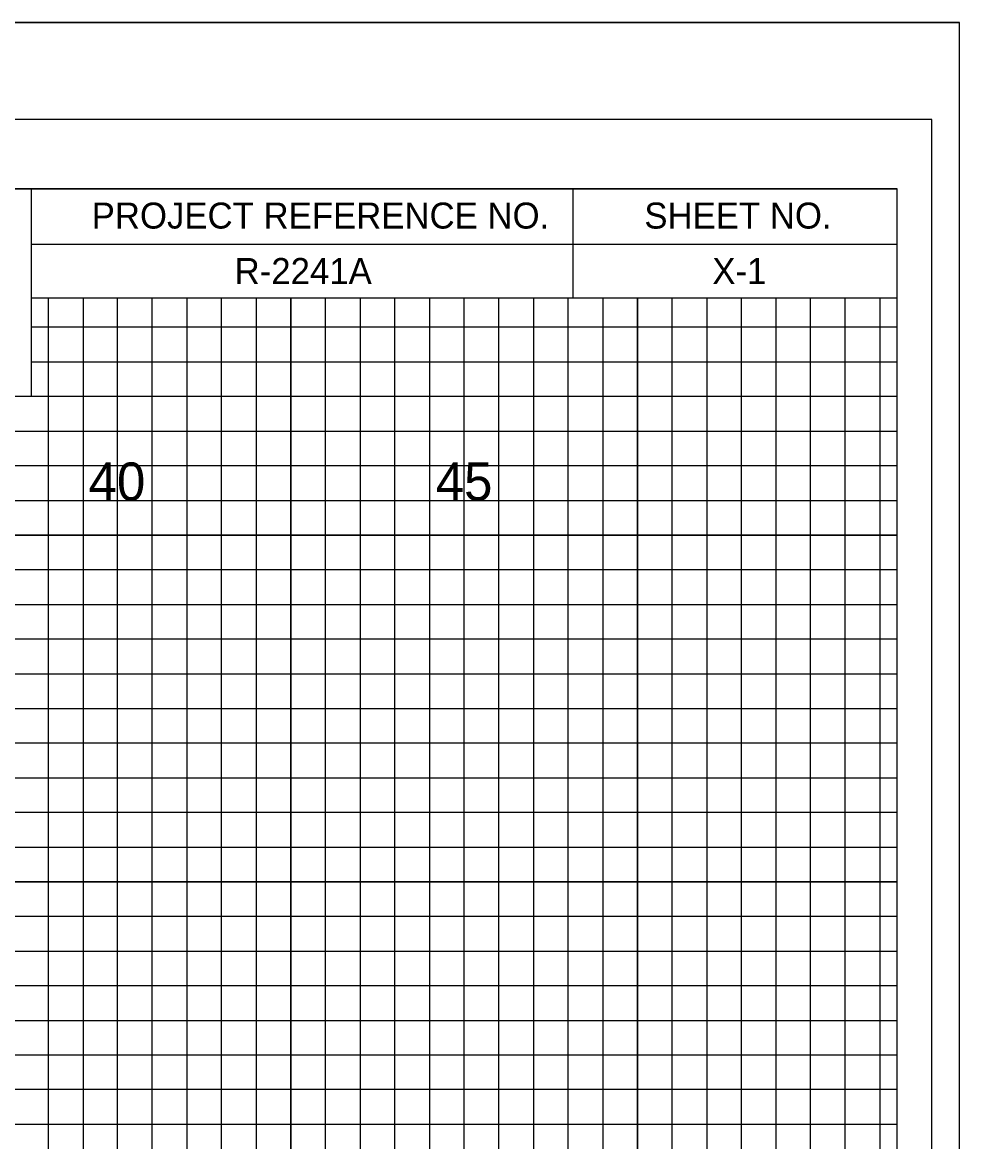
# Model space of a CAD drawing. Extents: x -4 to 103, y -2 to 6583.
# Drawn here: x 89.88 to 103.4, y 51.25 to 67.4 of the extents above; entities that cross this region are included whole.
import ezdxf

# ---------------------------------------------------------------- set-up
doc = ezdxf.new("R2010")
doc.units = 0
for name, color, linetype in [('Prop XS Offset Labels', 7, 'Continuous'), ('Prop XS Project Number', 7, 'Continuous'), ('Prop XS Sheet Number', 7, 'Continuous'), ('Sheet Cross Section CELL', 7, 'Continuous'), ('Sheet Cross Section Grid Major CELL', 7, 'Continuous'), ('Sheet Cross Section Grid Middle CELL', 7, 'Continuous'), ('Sheet Cutting Line CELL', 7, 'Continuous'), ('Sheet DOT Grid CELL', 7, 'Continuous'), ('Sheet Plot Border Inside CELL', 7, 'Continuous'), ('Sheet Plot Border Outside CELL', 7, 'Continuous')]:
    doc.layers.add(name, color=color, linetype=linetype)

msp = doc.modelspace()

# ---------------------------------------------------------------- linework, layer by layer
at = {"layer": 'Sheet Cross Section CELL'}
for p, q in [((90, 65), (102.5, 65)), ((90, 65), (102.5, 65)), ((97.825, 63.425), (97.825, 65)), ((101.875, 65), (101.875, 65)), ((102.5, 65), (102.5, 65)), ((102.5, 63.425), (102.5, 65)), ((102.5, 65), (102.5, 65)), ((102.5, 65), (102.5, 65)), ((102.5, 63.425), (102.5, 65)), ((90, 64.2), (102.5, 64.2)), ((90, 63.425), (102.5, 63.425)), ((99.4, 63.425), (99.4, 63.425)), ((99.4, 63.425), (99.4, 63.425))]:
    msp.add_line(p, q, dxfattribs=at)
for points in [[(102.5, 65), (0, 65), (0, 0), (102.5, 0)], [(83.75, 65), (90, 65), (90, 62), (83.75, 62)]]:
    msp.add_lwpolyline(points, close=True, dxfattribs=at)
at = {"layer": 'Sheet Cross Section Grid Major CELL'}
for points in [[(91.25, 0), (91.25, 63.425), (93.75, 63.425), (93.75, 0)], [(96.25, 0), (96.25, 63.425), (98.75, 63.425), (98.75, 0)], [(101.25, 0), (101.25, 63.425)], [(90, 62.5), (102.5, 62.5)], [(0, 57.5), (102.5, 57.5), (102.5, 60), (0, 60)], [(0, 52.5), (102.5, 52.5), (102.5, 55), (0, 55)]]:
    msp.add_lwpolyline(points, dxfattribs=at)
at = {"layer": 'Sheet Cross Section Grid Middle CELL'}
for points in [[(90.25, 0), (90.25, 63.425), (90.75, 63.425), (90.75, 0)], [(91.75, 0), (91.75, 63.425), (92.25, 63.425), (92.25, 0)], [(92.75, 0), (92.75, 63.425), (93.25, 63.425), (93.25, 0)], [(94.25, 0), (94.25, 63.425), (94.75, 63.425), (94.75, 0)], [(95.25, 0), (95.25, 63.425), (95.75, 63.425), (95.75, 0)], [(96.75, 0), (96.75, 63.425), (97.25, 63.425), (97.25, 0)], [(97.75, 0), (97.75, 63.425), (98.25, 63.425), (98.25, 0)], [(99.25, 0), (99.25, 63.425), (99.75, 63.425), (99.75, 0)], [(100.25, 0), (100.25, 63.425)], [(100.25, 63.425), (100.75, 63.425), (100.75, 0), (101.75, 0), (101.75, 63.425), (102.25, 63.425), (102.25, 0)], [(102.5, 62), (102.5, 63), (90, 63)], [(0, 61.5), (102.5, 61.5), (102.5, 62), (0, 62)], [(0, 60.5), (102.5, 60.5), (102.5, 61), (0, 61)], [(0, 59), (102.5, 59), (102.5, 59.5), (0, 59.5)], [(0, 58), (102.5, 58), (102.5, 58.5), (0, 58.5)], [(0, 56.5), (102.5, 56.5), (102.5, 57), (0, 57)], [(0, 55.5), (102.5, 55.5), (102.5, 56), (0, 56)], [(0, 54), (102.5, 54), (102.5, 54.5), (0, 54.5)], [(0, 53), (102.5, 53), (102.5, 53.5), (0, 53.5)], [(0, 51.5), (102.5, 51.5), (102.5, 52), (0, 52)]]:
    msp.add_lwpolyline(points, dxfattribs=at)
at = {"layer": 'Sheet Cutting Line CELL'}
msp.add_line((-3.5, 67.4), (103.4, 67.4), dxfattribs=at)
at = {"layer": 'Sheet DOT Grid CELL'}
for p, q in [((91.25, 0), (91.25, 63.425)), ((93.75, 0), (93.75, 63.425)), ((96.25, 0), (96.25, 63.425)), ((98.75, 0), (98.75, 63.425)), ((101.25, 0), (101.25, 63.425)), ((90, 62.5), (102.5, 62.5)), ((0, 60), (102.5, 60)), ((0, 57.5), (102.5, 57.5)), ((0, 55), (102.5, 55)), ((0, 52.5), (102.5, 52.5))]:
    msp.add_line(p, q, dxfattribs=at)
at = {"layer": 'Sheet Plot Border Inside CELL'}
msp.add_lwpolyline([(103, 66), (-2.8, 66), (-2.8, -1), (103, -1)], close=True, dxfattribs=at)
at = {"layer": 'Sheet Plot Border Outside CELL'}
msp.add_lwpolyline([(103.4, 67.4), (-3.5, 67.4), (-3.5, -2.425), (103.4, -2.425)], close=True, dxfattribs=at)

# ---------------------------------------------------------------- texts
at = {"layer": 'Prop XS Offset Labels'}
for s, p in [('40', (90.831, 60.5)), ('45', (95.84, 60.5))]:
    msp.add_text(s, height=0.55, dxfattribs=at).set_placement(p)
at = {"layer": 'Prop XS Project Number'}
msp.add_text('R-2241A', height=0.375, dxfattribs=at).set_placement((92.938, 63.625))
at = {"layer": 'Prop XS Sheet Number'}
msp.add_text('X-1', height=0.375, dxfattribs=at).set_placement((99.831, 63.625))
at = {"layer": 'Sheet Cross Section CELL'}
for s, p in [('PROJECT REFERENCE NO.', (90.875, 64.425)), ('SHEET NO.', (98.85, 64.425))]:
    msp.add_text(s, height=0.375, dxfattribs=at).set_placement(p)

doc.saveas('drawing.dxf')
